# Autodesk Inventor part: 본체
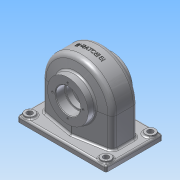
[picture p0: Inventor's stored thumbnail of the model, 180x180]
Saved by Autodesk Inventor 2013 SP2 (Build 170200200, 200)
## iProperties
Created: 2025-05
Part Number: 본체
Material: 알루미늄 6061
Document SubType Name: Modeling
Designer: a
Density: 2.71 g/cm^3
Mass: 734.294 g
Surface Area: 905.47 cm^2
Volume: 270.957 cm^3
Author: a
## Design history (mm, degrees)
sketch "스케치4"
  geometry: L1 (72, 46)-(-72, 46); L2 (-72, 46)-(-72, -46); L3 (-72, -46)-(72, -46); L4 (72, -46)-(72, 46); L5 (72, 46)-(-72, -46); L6 (-72, 46)-(72, -46); 1 further point
  constraints: 12 end point, 2 midpoint, 2 parallel, 1 horizontal, 1 perpendicular
  dimensions: "d7" = 92 distance of L1.end L2.end; "d9" = 144 distance of L1.start L1.end
extrude "돌출1" new body sketch "스케치4" distance "d10" = 9; taper "d11" = 0 deg
sketch "스케치5"
  geometry: L1 (-72, 46)-(-72, -46) reference; L2 (-57, 20)-(0, 30.051); L3 (0, 30.051)-(57, 20); L4 (57, 20)-(57, -20); L5 (57, -20)-(0, -30.051); L6 (0, -30.051)-(-57, -20); L7 (-57, -20)-(-57, 20); L8 (-54.903, 0)-(57, 0); 1 further point
  constraints: 14 end point, 2 parallel, 2 vertical alignment, 1 midpoint
  dimensions: "d12" = 20 deg angle of L5 L3; "d13" = 20 deg angle of L6 L2; "d14" = 40 distance of L3.end L4.end; "d16" = 40 distance of L6.end L2.start; "d17" = 114 distance between parallel lines of L4 L7; "d18" = 20 vertical distance of point (0, 0) L3.end; "d19" = 20 vertical distance of point (0, 0) L2.start; "d20" = 10 deg angle of L8 L3; "d21" = 10 deg angle of L8 L2
extrude "돌출2" join sketch "스케치5" distance "d22" = 48; taper "d23" = 0 deg
sketch "스케치6"
  geometry: L1 (0, 30.051)-(-57, 20) reference; L2 (-57, 20)-(-57, -20) reference; L3 (-57, -20)-(0, -30.051) reference; L4 (57, -20)-(57, 20) reference; L5 (0, 30.051)-(0, -30.051); 1 further point
  constraints: 2 end point, 1 parallel
revolve "회전1" sketch "스케치6" stored, may be unused: angle "d27" = 90 deg
fillet "모깎기2" dims "d28" = 8
feature "쉘2" dims "d29" = 12, "d30" = 5
node "작업 평면1"
sketch "스케치8"
  geometry: C1 r 24 at (0, 60); 1 further point
  constraints: 1 centre point, 1 vertical alignment
  dimensions: "d32" = 48 diameter of C1; "d34" = 60 distance of point (0, 0) C1.centre
extrude "돌출3" join sketch "스케치8" stored distance "d35" = 10; taper "d36" = 0 deg
node "작업 평면2"
sketch "스케치9"
  geometry: L1 (-72, 0)-(72, 0) reference; C1 r 33 at (0, 60); 2 further points
  constraints: 1 centre point, 1 midpoint, 1 vertical alignment
  dimensions: "d38" = 66 diameter of C1; "d40" = 60 distance from line of L1 C1.centre
extrude "돌출4" join sketch "스케치9" stored distance "d41" = 10; taper "d42" = 0 deg
sketch "스케치10"
  geometry: L1 (0, 46)-(9, 46) reference; L2 (9, 46)-(9, 30.051) reference; L3 (9, 30.051)-(27, 30.051) reference; L4 (27, 30.051)-(27, 36) reference; L5 (27, 36)-(93, 36) reference; L6 (93, 36)-(93, 23.703) reference; L7 (93, 23.703)-(107.389, 21.166) reference; L8 (114, 13.287)-(114, -13.287) reference; L9 (107.389, -21.166)-(93, -23.703) reference; L10 (93, -23.703)-(93, -36) reference; L11 (93, -36)-(27, -36) reference; L12 (27, -36)-(27, -30.051) reference; L13 (27, -30.051)-(9, -30.051) reference; L14 (9, -30.051)-(9, -46) reference; L15 (9, -46)-(0, -46) reference; L16 (0, -46)-(0, -24.974) reference; L17 (0, -24.974)-(36, -24.974) reference; L18 (36, -24.974)-(36, -12) reference; L19 (36, -12)-(84, -12) reference; L20 (84, -12)-(84, -20.213) reference; L21 (84, -20.213)-(106.521, -16.242) reference; L22 (109, -13.287)-(109, 13.287) reference; L23 (106.521, 16.242)-(84, 20.213) reference; L24 (84, 20.213)-(84, 12) reference; L25 (84, 12)-(36, 12) reference; L26 (36, 12)-(36, 24.974) reference; L27 (36, 24.974)-(0, 24.974) reference; L28 (0, 24.974)-(0, 46) reference; L29 (80, 36)-(80, 21.6); L30 (79.4, 21)-(77.5, 21); L31 (77.5, 21)-(77.5, -21); L32 (77.5, -21)-(79.4, -21); L33 (80, -21.6)-(80, -36); L34 (60, -36)-(60, 36); L35 (80, 36)-(60, 36); L36 (80, -36)-(60, -36); A1 r 8 centre (106, 13.287) between (114, 13.287) and (107.389, 21.166) reference; A2 r 8 centre (106, -13.287) between (107.389, -21.166) and (114, -13.287) reference; A3 r 3 centre (106, -13.287) between (106.521, -16.242) and (109, -13.287) reference; A4 r 3 centre (106, 13.287) between (109, 13.287) and (106.521, 16.242) reference; A5 r 0.6 centre (79.4, 21.6) between (79.4, 21) and (80, 21.6); A6 r 0.6 centre (79.4, -21.6) between (80, -21.6) and (79.4, -21); 3 further points
  constraints: 16 end point, 6 point on line, 4 parallel, 4 point on circle, 4 tangent, 3 perpendicular, 2 centre point, 2 midpoint, 1 collinear, 1 equal radius
  dimensions: "d43" = 120 diameter of point (0, 0) L34; "d44" = 40 diameter of L33 L34; "d45" = 35 diameter of L31 L34; "d46" = 15 distance of point (80, -21) L33.end; "d47" = 15 distance of L29.start point (80, 21); "d48" = 0.6 radius of A5
revolve "회전2" sketch "스케치10" stored, may be unused: angle "d49" = 90 deg
chamfer "모따기1" distance "d50" = 1; stored, may be unused: second distance "d51" = 2, angle "d52" = 45 deg
sketch "스케치11" dims "d53" = 50
  geometry: L1 (0, 0)-(0, 25); C1 r 21 at (0, 0) reference; 2 further points
  constraints: 2 coincident, 2 end point, 1 vertical, 1 vertical alignment, 2 other
hole "구멍1" sketch "스케치11" at (0, 25) diameter "d55" = 3.242; stored, may be unused: countersink angle "d59" = 90 deg, drill point angle "d61" = 118 deg; dims "d56" = 8, "d57" = 4, "d58" = 2, "d60" = 10
sketch "스케치12"
  geometry: C1 r 8 at (62, 36); C2 r 8 at (62, -36); C3 r 8 at (-62, 36); C4 r 8 at (-62, -36); 1 further point
  constraints: 4 centre point, 2 horizontal alignment, 2 vertical alignment
  dimensions: "d65" = 72 distance of C2.centre C1.centre; "d67" = 124 distance of C1.centre C3.centre; "d68" = 16 diameter of C1; "d69" = 16 diameter of C3; "d70" = 16 diameter of C4; "d71" = 16 diameter of C2; "d72" = 36 vertical distance of C1.centre point (0, 0); "d73" = 62 horizontal distance of point (0, 0) C3.centre
extrude "돌출5" join sketch "스케치12" distance "d74" = 3; taper "d75" = 0 deg
hole "구멍2" diameter "d78" = 9; stored, may be unused: countersink angle "d82" = 90 deg, drill point angle "d84" = 118 deg; dims "d79" = 9, "d80" = 4, "d81" = 2, "d83" = 10, "d85" = 10, "d86" = 10
hole "구멍3" diameter "d89" = 9; stored, may be unused: countersink angle "d93" = 90 deg, drill point angle "d95" = 118 deg; dims "d87" = 10, "d88" = 10, "d90" = 9, "d91" = 4, "d92" = 2, "d94" = 10
hole "구멍4" diameter "d98" = 9; stored, may be unused: countersink angle "d102" = 90 deg, drill point angle "d104" = 118 deg; dims "d96" = 10, "d97" = 10, "d99" = 9, "d100" = 4, "d101" = 2, "d103" = 10
hole "구멍5" diameter "d107" = 9; stored, may be unused: countersink angle "d111" = 90 deg, drill point angle "d113" = 118 deg; dims "d105" = 10, "d106" = 10, "d108" = 9, "d109" = 4, "d110" = 2, "d112" = 10
fillet "모깎기3" dims "d114" = 3
fillet "모깎기4" dims "d115" = 3
fillet "모깎기5" dims "d116" = 3
fillet "모깎기6" dims "d117" = 3
node "작업 평면3"
sketch "스케치13"
  geometry: 2 further points
  constraints: 1 coincident, 1 other
feature "엠보싱1" sketch "스케치13" dims "d7" = 92, "d9" = 144, "d118" = 0.5, "d119" = 0
node "솔리드1"
mirror "대칭1"
pattern_circular "원형 패턴1" dims angle "d63" = 360 deg
mirror "대칭2"
node "절단 모서리 투영2"
other parameters: "d31" = 12, "d37" = 36
